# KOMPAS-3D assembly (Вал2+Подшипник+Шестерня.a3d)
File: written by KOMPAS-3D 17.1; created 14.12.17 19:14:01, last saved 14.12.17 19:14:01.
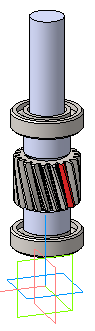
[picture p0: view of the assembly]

Referenced files in C:\Users\Yaroslav\Desktop\Новая папка\: Втулка.m3d, Шпонка (10х6х15).m3d, Вал2.m3d, Косозубая шестерня 1 (правое)_PreviewCfg.m3d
